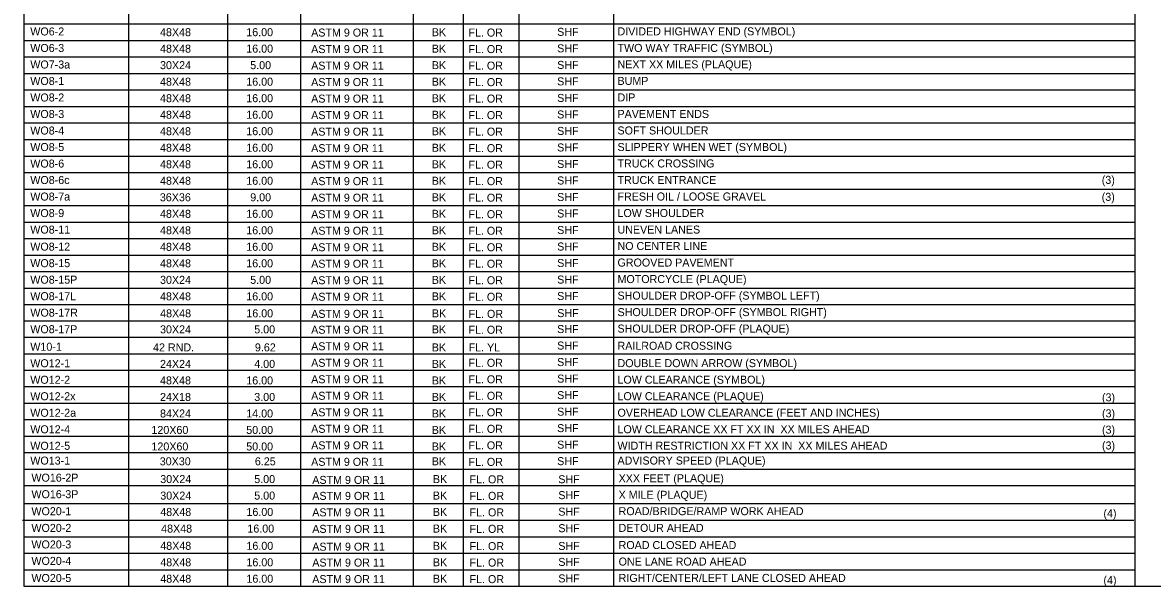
# Model space of a CAD drawing. Extents: x -439.1 to -407.9, y -458.1 to -437.7.
# Drawn here: x -439.13 to -418.9, y -458.05 to -447.95 of the extents above; entities that cross this region are included whole.
import ezdxf

# ---------------------------------------------------------------- set-up
doc = ezdxf.new("R2010")
doc.units = 0
for name, color, linetype in [('Draft_Named_Boundary', 7, 'Continuous'), ('Level 4', 7, 'Continuous'), ('Level 45', 7, 'Continuous')]:
    doc.layers.add(name, color=color, linetype=linetype)

msp = doc.modelspace()

# ---------------------------------------------------------------- linework, layer by layer
at = {"layer": 'Draft_Named_Boundary'}
msp.add_lwpolyline([(-439.109, -458.051), (-407.859, -458.051), (-407.859, -437.676), (-439.109, -437.676)], close=True, dxfattribs=at)
at = {"layer": 'Level 4'}
for p, q in [((-439.109, -437.676), (-439.109, -458.051)), ((-419.212, -437.676), (-419.212, -458.051)), ((-437.233, -438.806), (-437.233, -458.051)), ((-435.462, -438.806), (-435.462, -458.051)), ((-434.152, -438.806), (-434.152, -458.051)), ((-432.136, -438.806), (-432.136, -458.051)), ((-431.24, -438.806), (-431.24, -458.051)), ((-430.244, -438.806), (-430.244, -458.051)), ((-428.547, -438.806), (-428.547, -458.051)), ((-439.109, -447.976), (-419.212, -447.976)), ((-439.109, -448.272), (-419.212, -448.272)), ((-439.109, -448.568), (-419.212, -448.568)), ((-439.109, -448.864), (-419.212, -448.864)), ((-439.109, -449.159), (-419.212, -449.159)), ((-439.109, -449.455), (-419.212, -449.455)), ((-439.109, -449.751), (-419.212, -449.751)), ((-439.109, -450.047), (-419.212, -450.047)), ((-439.109, -450.343), (-419.212, -450.343)), ((-439.109, -450.638), (-419.212, -450.638)), ((-439.109, -450.934), (-419.212, -450.934)), ((-439.109, -451.23), (-419.212, -451.23)), ((-439.109, -451.526), (-419.212, -451.526)), ((-439.109, -451.822), (-419.212, -451.822)), ((-439.109, -452.117), (-419.212, -452.117)), ((-439.109, -452.413), (-419.212, -452.413)), ((-439.109, -452.709), (-419.212, -452.709)), ((-439.109, -453.005), (-419.212, -453.005)), ((-439.109, -453.298), (-419.212, -453.298)), ((-439.109, -453.591), (-419.212, -453.591)), ((-439.109, -453.885), (-419.212, -453.885)), ((-439.109, -454.178), (-419.212, -454.178)), ((-439.109, -454.474), (-419.212, -454.474)), ((-439.109, -454.769), (-419.212, -454.769)), ((-439.109, -455.065), (-419.212, -455.065)), ((-439.109, -455.361), (-419.212, -455.361)), ((-439.109, -455.656), (-419.212, -455.656)), ((-439.109, -455.952), (-419.212, -455.952)), ((-439.109, -456.248), (-419.212, -456.248)), ((-439.109, -456.571), (-419.212, -456.571)), ((-439.129, -456.867), (-419.232, -456.867)), ((-439.109, -457.163), (-419.212, -457.163)), ((-439.109, -457.458), (-419.212, -457.458)), ((-439.109, -457.754), (-419.212, -457.754)), ((-439.109, -458.051), (-419.212, -458.051))]:
    msp.add_line(p, q, dxfattribs=at)

# ---------------------------------------------------------------- texts
for s, height, p in [('WO6-2', 0.1433, (-438.991, -448.183)), ('ASTM 9 OR 11', 0.14328, (-433.962, -448.203)), ('BK', 0.1433, (-431.802, -448.196)), ('FL. OR', 0.1433, (-431.146, -448.203)), ('SHF', 0.1433, (-429.557, -448.19)), ('DIVIDED HIGHWAY END (SYMBOL)', 0.14328, (-428.477, -448.182)), ('WO6-3', 0.1433, (-438.991, -448.479)), ('ASTM 9 OR 11', 0.14328, (-433.962, -448.499)), ('BK', 0.1433, (-431.802, -448.491)), ('FL. OR', 0.1433, (-431.146, -448.499)), ('SHF', 0.1433, (-429.557, -448.486)), ('TWO WAY TRAFFIC (SYMBOL)', 0.14328, (-428.477, -448.478)), ('WO7-3a', 0.1433, (-438.991, -448.775)), ('ASTM 9 OR 11', 0.14328, (-433.962, -448.795)), ('BK', 0.1433, (-431.802, -448.787)), ('FL. OR', 0.1433, (-431.146, -448.795)), ('SHF', 0.1433, (-429.557, -448.782)), ('NEXT XX MILES (PLAQUE)', 0.14328, (-428.477, -448.773)), ('WO8-1 ', 0.1433, (-438.991, -449.071)), ('ASTM 9 OR 11', 0.14328, (-433.962, -449.09)), ('BK', 0.1433, (-431.802, -449.083)), ('FL. OR', 0.1433, (-431.146, -449.091)), ('SHF', 0.1433, (-429.557, -449.078)), ('BUMP', 0.1433, (-428.477, -449.069)), ('WO8-2 ', 0.1433, (-438.991, -449.366)), ('ASTM 9 OR 11', 0.14328, (-433.962, -449.386)), ('BK', 0.1433, (-431.802, -449.379)), ('FL. OR', 0.1433, (-431.146, -449.386)), ('SHF', 0.1433, (-429.557, -449.374)), ('DIP', 0.1433, (-428.477, -449.365)), ('WO8-3', 0.1433, (-438.991, -449.662)), ('ASTM 9 OR 11', 0.14328, (-433.962, -449.682)), ('BK', 0.1433, (-431.802, -449.675)), ('FL. OR', 0.1433, (-431.146, -449.682)), ('SHF', 0.1433, (-429.557, -449.67)), ('PAVEMENT ENDS', 0.14328, (-428.477, -449.661)), ('WO8-4 ', 0.1433, (-438.991, -449.958)), ('ASTM 9 OR 11', 0.14328, (-433.962, -449.978)), ('BK', 0.1433, (-431.802, -449.97)), ('FL. OR', 0.1433, (-431.146, -449.978)), ('SHF', 0.1433, (-429.557, -449.965)), ('SOFT SHOULDER', 0.14328, (-428.477, -449.957)), ('SLIPPERY WHEN WET (SYMBOL) ', 0.14328, (-428.477, -450.253)), ('WO8-5 ', 0.1433, (-438.991, -450.254)), ('ASTM 9 OR 11', 0.14328, (-433.962, -450.274)), ('BK', 0.1433, (-431.802, -450.266)), ('FL. OR', 0.1433, (-431.146, -450.274)), ('SHF', 0.1433, (-429.557, -450.261)), ('WO8-6 ', 0.1433, (-438.991, -450.55)), ('ASTM 9 OR 11', 0.14328, (-433.962, -450.569)), ('BK', 0.1433, (-431.802, -450.562)), ('FL. OR', 0.1433, (-431.146, -450.57)), ('SHF', 0.1433, (-429.557, -450.557)), ('TRUCK CROSSING', 0.14328, (-428.477, -450.548)), ('WO8-6c', 0.1433, (-438.991, -450.845)), ('BK', 0.1433, (-431.802, -450.858)), ('SHF', 0.1433, (-429.557, -450.853)), ('TRUCK ENTRANCE ', 0.14328, (-428.477, -450.844)), ('(3)', 0.1433, (-419.806, -450.842)), ('ASTM 9 OR 11', 0.14328, (-433.962, -450.865)), ('FL. OR', 0.1433, (-431.146, -450.865)), ('WO8-7a ', 0.1433, (-438.991, -451.141)), ('ASTM 9 OR 11', 0.14328, (-433.962, -451.161)), ('BK', 0.1433, (-431.802, -451.154)), ('FL. OR', 0.1433, (-431.146, -451.161)), ('SHF', 0.1433, (-429.557, -451.149)), ('FRESH OIL / LOOSE GRAVEL', 0.14328, (-428.477, -451.14)), ('(3)', 0.1433, (-419.807, -451.146)), ('WO8-9', 0.1433, (-438.991, -451.437)), ('ASTM 9 OR 11', 0.14328, (-433.962, -451.457)), ('BK', 0.1433, (-431.802, -451.45)), ('FL. OR', 0.1433, (-431.146, -451.457)), ('SHF', 0.1433, (-429.557, -451.444)), ('LOW SHOULDER', 0.14328, (-428.477, -451.436)), ('WO8-11', 0.1433, (-438.991, -451.733)), ('ASTM 9 OR 11', 0.14328, (-433.962, -451.753)), ('BK', 0.1433, (-431.802, -451.745)), ('FL. OR', 0.1433, (-431.146, -451.753)), ('SHF', 0.1433, (-429.557, -451.74)), ('UNEVEN LANES', 0.14328, (-428.477, -451.732)), ('WO8-12', 0.1433, (-438.991, -452.038)), ('ASTM 9 OR 11', 0.14328, (-433.962, -452.049)), ('BK', 0.1433, (-431.802, -452.041)), ('FL. OR', 0.1433, (-431.146, -452.049)), ('SHF', 0.1433, (-429.557, -452.036)), ('NO CENTER LINE', 0.14328, (-428.477, -452.027)), ('WO8-15', 0.1433, (-438.991, -452.334)), ('ASTM 9 OR 11', 0.14328, (-433.962, -452.344)), ('BK', 0.1433, (-431.802, -452.337)), ('FL. OR', 0.1433, (-431.146, -452.344)), ('SHF', 0.1433, (-429.557, -452.332)), ('GROOVED PAVEMENT', 0.14328, (-428.477, -452.323)), ('WO8-15P', 0.1433, (-438.991, -452.63)), ('ASTM 9 OR 11', 0.14328, (-433.962, -452.64)), ('BK', 0.1433, (-431.802, -452.633)), ('FL. OR', 0.1433, (-431.146, -452.64)), ('SHF', 0.1433, (-429.557, -452.628)), ('MOTORCYCLE (PLAQUE)', 0.14328, (-428.477, -452.619)), ('WO8-17L', 0.1433, (-438.991, -452.926)), ('ASTM 9 OR 11', 0.14328, (-433.962, -452.936)), ('BK', 0.1433, (-431.802, -452.929)), ('FL. OR', 0.1433, (-431.146, -452.936)), ('SHF', 0.1433, (-429.557, -452.923)), ('SHOULDER DROP-OFF (SYMBOL LEFT)', 0.14328, (-428.477, -452.915)), ('WO8-17R', 0.1433, (-438.99, -453.221)), ('ASTM 9 OR 11', 0.14328, (-433.961, -453.242)), ('BK', 0.1433, (-431.8, -453.233)), ('FL. OR', 0.1433, (-431.144, -453.242)), ('SHF', 0.1433, (-429.556, -453.229)), ('SHOULDER DROP-OFF (SYMBOL RIGHT)', 0.14328, (-428.476, -453.211)), ('WO8-17P', 0.1433, (-438.991, -453.517)), ('ASTM 9 OR 11', 0.14328, (-433.962, -453.527)), ('BK', 0.1433, (-431.802, -453.52)), ('FL. OR', 0.1433, (-431.146, -453.527)), ('SHF', 0.1433, (-429.557, -453.515)), ('SHOULDER DROP-OFF (PLAQUE)', 0.14328, (-428.477, -453.506)), ('W10-1', 0.1433, (-438.991, -453.831)), ('ASTM 9 OR 11', 0.14328, (-433.962, -453.823)), ('BK', 0.1433, (-431.802, -453.843)), ('FL. YL', 0.1433, (-431.142, -453.843)), ('SHF', 0.1433, (-429.557, -453.81)), ('RAILROAD CROSSING', 0.14328, (-428.477, -453.814)), ('WO12-1', 0.1433, (-438.991, -454.127)), ('ASTM 9 OR 11', 0.14328, (-433.962, -454.119)), ('BK', 0.1433, (-431.802, -454.139)), ('FL. OR', 0.1433, (-431.146, -454.119)), ('SHF', 0.1433, (-429.557, -454.106)), ('DOUBLE DOWN ARROW (SYMBOL)', 0.14328, (-428.477, -454.125)), ('WO12-2 ', 0.1433, (-438.991, -454.423)), ('ASTM 9 OR 11', 0.14328, (-433.962, -454.414)), ('BK', 0.1433, (-431.802, -454.435)), ('FL. OR', 0.1433, (-431.146, -454.415)), ('SHF', 0.1433, (-429.557, -454.402)), ('LOW CLEARANCE (SYMBOL)', 0.14328, (-428.477, -454.421)), ('SHF', 0.1433, (-429.557, -454.698)), ('WO12-2x', 0.1433, (-438.991, -454.718)), ('ASTM 9 OR 11', 0.14328, (-433.962, -454.71)), ('BK', 0.1433, (-431.802, -454.731)), ('FL. OR', 0.1433, (-431.146, -454.71)), ('LOW CLEARANCE (PLAQUE)', 0.14328, (-428.477, -454.717)), ('(3)', 0.1433, (-419.802, -454.738)), ('WO12-2a', 0.1433, (-438.991, -455.014)), ('ASTM 9 OR 11', 0.14328, (-433.962, -455.006)), ('BK', 0.1433, (-431.802, -455.027)), ('FL. OR', 0.1433, (-431.146, -455.006)), ('SHF', 0.1433, (-429.557, -454.994)), ('OVERHEAD LOW CLEARANCE (FEET AND INCHES)', 0.14328, (-428.477, -455.013)), ('(3)', 0.1433, (-419.802, -455.025)), ('WO12-4', 0.1433, (-438.991, -455.31)), ('ASTM 9 OR 11', 0.14328, (-433.962, -455.302)), ('FL. OR', 0.1433, (-431.146, -455.302)), ('SHF', 0.1433, (-429.557, -455.289)), ('LOW CLEARANCE XX FT XX IN  XX MILES AHEAD', 0.14328, (-428.477, -455.309)), ('BK', 0.1433, (-431.802, -455.322)), ('(3)', 0.1433, (-419.802, -455.317)), ('WO12-5', 0.1433, (-438.991, -455.606)), ('ASTM 9 OR 11', 0.14328, (-433.962, -455.598)), ('BK', 0.1433, (-431.802, -455.618)), ('FL. OR', 0.1433, (-431.146, -455.598)), ('SHF', 0.1433, (-429.557, -455.585)), ('WIDTH RESTRICTION XX FT XX IN  XX MILES AHEAD', 0.14328, (-428.477, -455.604)), ('(3)', 0.1433, (-419.802, -455.6)), ('WO13-1 ', 0.1433, (-438.991, -455.871)), ('ASTM 9 OR 11', 0.14328, (-433.962, -455.893)), ('BK', 0.1433, (-431.802, -455.884)), ('FL. OR', 0.1433, (-431.146, -455.894)), ('SHF', 0.1433, (-429.557, -455.881)), ('ADVISORY SPEED (PLAQUE)', 0.14328, (-428.477, -455.87)), ('WO16-2P', 0.1433, (-438.971, -456.177)), ('ASTM 9 OR 11', 0.14328, (-433.942, -456.217)), ('BK', 0.1433, (-431.782, -456.202)), ('FL. OR', 0.1433, (-431.126, -456.207)), ('SHF', 0.1433, (-429.537, -456.205)), ('XXX FEET (PLAQUE)', 0.14328, (-428.457, -456.188)), ('WO16-3P', 0.1433, (-438.971, -456.473)), ('ASTM 9 OR 11', 0.14328, (-433.942, -456.503)), ('BK', 0.1433, (-431.782, -456.498)), ('FL. OR', 0.1433, (-431.126, -456.503)), ('SHF', 0.1433, (-429.537, -456.49)), ('X MILE (PLAQUE)', 0.14328, (-428.457, -456.484)), ('WO20-1', 0.1433, (-438.971, -456.778)), ('ASTM 9 OR 11', 0.14328, (-433.942, -456.798)), ('BK', 0.1433, (-431.782, -456.791)), ('FL. OR', 0.1433, (-431.126, -456.799)), ('SHF', 0.1433, (-429.537, -456.786)), ('ROAD/BRIDGE/RAMP WORK AHEAD ', 0.14328, (-428.457, -456.777)), ('(4)', 0.1433, (-419.776, -456.815)), ('WO20-2', 0.1433, (-438.971, -457.077)), ('ASTM 9 OR 11', 0.14328, (-433.942, -457.094)), ('BK', 0.1433, (-431.782, -457.089)), ('FL. OR', 0.1433, (-431.126, -457.094)), ('SHF', 0.1433, (-429.537, -457.082)), ('DETOUR AHEAD', 0.14328, (-428.457, -457.076)), ('WO20-3', 0.1433, (-438.971, -457.373)), ('ASTM 9 OR 11', 0.14328, (-433.942, -457.413)), ('BK', 0.1433, (-431.782, -457.398)), ('FL. OR', 0.1433, (-431.126, -457.403)), ('SHF', 0.1433, (-429.537, -457.4)), ('ROAD CLOSED AHEAD', 0.14328, (-428.457, -457.384)), ('WO20-4', 0.1433, (-438.971, -457.668)), ('ASTM 9 OR 11', 0.14328, (-433.942, -457.698)), ('BK', 0.1433, (-431.782, -457.693)), ('FL. OR', 0.1433, (-431.126, -457.698)), ('SHF', 0.1433, (-429.537, -457.686)), ('ONE LANE ROAD AHEAD', 0.14328, (-428.457, -457.68)), ('WO20-5', 0.1433, (-438.971, -457.974)), ('ASTM 9 OR 11', 0.14328, (-433.942, -457.994)), ('BK', 0.1433, (-431.782, -457.987)), ('FL. OR', 0.1433, (-431.126, -457.994)), ('SHF', 0.1433, (-429.537, -457.982)), ('RIGHT/CENTER/LEFT LANE CLOSED AHEAD ', 0.14328, (-428.457, -457.973)), ('(4)', 0.1433, (-419.776, -458.01))]:
    msp.add_text(s, height=height, dxfattribs=at).set_placement(p)
at = {"layer": 'Level 45'}
for s, p in [('48X48', (-436.668, -448.196)), ('16.00', (-435.124, -448.196)), ('48X48', (-436.668, -448.491)), ('16.00', (-435.124, -448.491)), ('30X24', (-436.668, -448.787)), ('5.00', (-435.053, -448.787)), ('48X48', (-436.668, -449.083)), ('16.00', (-435.124, -449.083)), ('48X48', (-436.668, -449.379)), ('16.00', (-435.124, -449.379)), ('48X48', (-436.668, -449.675)), ('16.00', (-435.124, -449.675)), ('48X48', (-436.668, -449.97)), ('16.00', (-435.124, -449.97)), ('48X48', (-436.668, -450.266)), ('16.00', (-435.124, -450.266)), ('48X48', (-436.668, -450.562)), ('16.00', (-435.124, -450.562)), ('48X48', (-436.668, -450.858)), ('16.00', (-435.124, -450.858)), ('36X36', (-436.671, -451.154)), ('9.00', (-435.053, -451.154)), ('48X48', (-436.668, -451.45)), ('16.00', (-435.124, -451.45)), ('48X48', (-436.668, -451.745)), ('16.00', (-435.124, -451.745)), ('48X48', (-436.668, -452.041)), ('16.00', (-435.124, -452.041)), ('48X48', (-436.668, -452.337)), ('16.00', (-435.124, -452.337)), ('30X24', (-436.668, -452.633)), ('5.00', (-435.053, -452.633)), ('48X48', (-436.668, -452.929)), ('16.00', (-435.124, -452.929)), ('48X48', (-436.666, -453.233)), ('16.00', (-435.123, -453.233)), ('30X24', (-436.668, -453.52)), ('5.00', (-434.981, -453.52)), ('42 RND.', (-436.793, -453.843)), ('9.62', (-434.969, -453.843)), ('24X24', (-436.668, -454.139)), ('4.00', (-434.981, -454.139)), ('48X48', (-436.668, -454.435)), ('16.00', (-435.124, -454.435)), ('24X18', (-436.668, -454.731)), ('3.00', (-434.981, -454.731)), ('84X24', (-436.668, -455.027)), ('14.00', (-435.124, -455.027)), ('120X60', (-436.822, -455.322)), ('50.00', (-435.124, -455.322)), ('120X60', (-436.822, -455.618)), ('50.00', (-435.124, -455.618)), ('30X30', (-436.673, -455.884)), ('6.25', (-434.97, -455.884)), ('30X24', (-436.664, -456.202)), ('5.00', (-434.981, -456.202)), ('30X24', (-436.664, -456.498)), ('5.00', (-434.981, -456.498)), ('48X48', (-436.664, -456.791)), ('16.00', (-435.121, -456.791)), ('48X48', (-436.648, -457.089)), ('16.00', (-435.104, -457.089)), ('48X48', (-436.664, -457.398)), ('16.00', (-435.121, -457.398)), ('48X48', (-436.664, -457.693)), ('16.00', (-435.121, -457.693)), ('48X48', (-436.664, -457.987)), ('16.00', (-435.121, -457.987))]:
    msp.add_text(s, height=0.1433, dxfattribs=at).set_placement(p)

doc.saveas('drawing.dxf')
